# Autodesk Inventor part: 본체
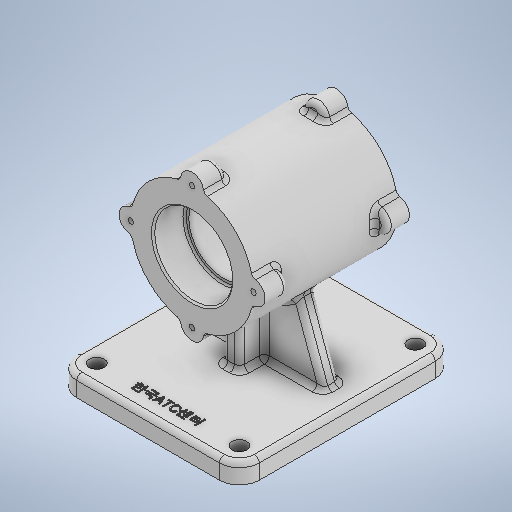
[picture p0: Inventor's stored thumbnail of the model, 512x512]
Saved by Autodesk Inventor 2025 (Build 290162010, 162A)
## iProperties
Created: 2024-08
Part Number: 본체
Material: 일반
Document SubType Name: Modeling
Designer: 학생
Density: 1 g/cm^3
Appearance: 기본값
Author: 학생
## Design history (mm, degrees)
sketch "스케치1"
  geometry: C1 r 37 at (0, 0); 1 further point
  constraints: 1 centre point, 1 coincident
  dimensions: "d0" = 74 diameter of C1
extrude "돌출1" new body sketch "스케치1" stored distance "d1" = 87; taper "d2" = 0 deg
sketch "스케치2"
  geometry: L1 (-90.461, 0)-(90.461, 0); L2 (0, 60.308)-(0, -67.296); C1 r 7 at (0, 37); C2 r 7 at (-37, 0); C3 r 7 at (0, -37); C4 r 7 at (37, 0); 2 further points
  constraints: 4 centre point, 4 end point, 2 point on line, 1 horizontal, 1 midpoint, 1 vertical, 1 vertical alignment, 10 other
  dimensions: "d3" = 14 diameter of C1; "d6" = 360 deg dimension on point (0, 0) C1.centre (derived)
extrude "돌출2" join sketch "스케치2" distance "d8" = 14; taper "d9" = 0 deg
node "작업 평면1"
sketch "스케치3"
  geometry: L1 (55, 70)-(-55, 70); L2 (-55, 70)-(-55, -60); L3 (-55, -60)-(55, -60); L4 (55, -60)-(55, 70); L5 (55, 70)-(-55, -60); L6 (-55, 70)-(55, -60); 2 further points
  constraints: 12 end point, 2 midpoint, 2 parallel, 1 horizontal, 1 perpendicular, 1 vertical alignment
  dimensions: "d11" = 130 distance of L3.end L1.start; "d12" = 110 distance of L2.end L3.end; "d30" = 70 distance from line of L1 point (0, 0)
extrude "돌출3" join sketch "스케치3" distance "d13" = 12; taper "d14" = 0 deg
sketch "스케치5"
  geometry: L1 (-5, 20)-(5, 20); L2 (5, 20)-(5, -20); L3 (5, -20)-(-5, -20); L4 (-5, -20)-(-5, 20); L5 (-55, -70)-(55, -70) reference; 2 further points
  constraints: 8 end point, 2 parallel, 1 horizontal, 1 midpoint, 1 perpendicular, 1 vertical alignment
  dimensions: "d22" = 10 distance of L1.start L1.end; "d23" = 40 distance of L1.end L2.end; "d24" = 50 distance between parallel lines of L5 L3
extrude "돌출5" join sketch "스케치5" stored distance "d25" = 10; taper "d26" = 0 deg
sketch "스케치7"
  geometry: L1 (-22.946, -20.396)-(-41, -70); L2 (55, -70)-(-55, -70) reference; L3 (41, -70)-(22.946, -20.396); L4 (22.946, -20.396)-(-22.946, -20.396); L5 (0, 11.975)-(0, -94.484); L6 (-55, -82)-(-55, -70) reference; 2 further points
  constraints: 8 end point, 3 point on line, 1 midpoint, 1 parallel, 1 vertical, 1 other
  dimensions: "d31" = 110 deg angle of L2 L1; "d32" = 14 horizontal distance of point (-55, -76) L1.end; "d33" = 49.60432 distance between parallel lines of L2 L4
extrude "돌출6" join sketch "스케치7" stored distance "d34" = 10; taper "d35" = 0 deg
sketch "스케치8"
  geometry: A1 r 37 centre (0, 0) between (36.338, 6.969) and (6.969, 36.338) reference; 2 further points
  constraints: 1 coincident
hole "구멍1" sketch "스케치8" at (0, 0) diameter "d36" = 47; stored, may be unused: countersink angle "d40" = 90 deg, drill point angle "d42" = 0 deg; dims "d37" = 6, "d38" = 4, "d39" = 2, "d41" = 19
sketch "스케치9"
  geometry: A1 r 37 centre (0, 0) between (36.338, 6.969) and (6.969, 36.338) reference; 2 further points
  constraints: 1 coincident
hole "구멍2" sketch "스케치9" at (0, 0) diameter "d43" = 47; stored, may be unused: countersink angle "d47" = 90 deg, drill point angle "d49" = 0 deg; dims "d44" = 6, "d45" = 4, "d46" = 2, "d48" = 19
sketch "스케치10"
  geometry: C1 r 23.5 at (0, 0) reference; 2 further points
  constraints: 1 coincident
hole "구멍3" sketch "스케치10" at (0, 0) diameter "d50" = 42; stored, may be unused: countersink angle "d54" = 90 deg, drill point angle "d56" = 0 deg; dims "d51" = 6, "d52" = 4, "d53" = 2, "d55" = 19
fillet "모깎기1" dims "d57" = 12
sketch "스케치11"
  geometry: A1 r 12 centre (43, -58) between (43, -70) and (55, -58) reference; A2 r 12 centre (-43, -58) between (-55, -58) and (-43, -70) reference; A3 r 12 centre (43, 48) between (55, 48) and (43, 60) reference; A4 r 12 centre (-43, 48) between (-43, 60) and (-55, 48) reference; 5 further points
  constraints: 4 coincident
hole "구멍4" sketch "스케치11" at (43, -58), (-43, -58), (43, 48), (-43, 48) diameter "d58" = 9; stored, may be unused: countersink angle "d62" = 90 deg, drill point angle "d64" = 0 deg; dims "d59" = 6, "d60" = 4, "d61" = 2, "d63" = 8
sketch "스케치12" dims "d65" = 74
  geometry: L1 (0, 71.26)-(0, -102.389); L2 (-89.397, 0)-(110.75, 0); 3 further points
  constraints: 4 end point, 3 point on line, 1 coincident, 1 horizontal, 1 vertical, 1 vertical alignment, 2 other
hole "구멍5" sketch "스케치12" at (0, 37) diameter "d66" = 3.242; stored, may be unused: countersink angle "d70" = 90 deg, drill point angle "d72" = 118 deg; dims "d67" = 8, "d68" = 4, "d69" = 2, "d71" = 10
fillet "모깎기2" dims "d76" = 3
fillet "모깎기3" dims "d77" = 3
fillet "모깎기4" dims "d78" = 3
fillet "모깎기5" dims "d79" = 3
fillet "모깎기6" dims "d80" = 3
fillet "모깎기7" dims "d81" = 1
chamfer "모따기1" distance "d82" = 1; stored, may be unused: second distance "d83" = 2, angle "d84" = 45 deg
sketch "스케치13"
  geometry: 2 further points
  constraints: 1 vertical alignment, 1 other
  dimensions: "d85" = 58 distance of point (0, 0) point (0, -58)
feature "엠보싱1" sketch "스케치13" dims "d86" = 0.5, "d87" = 0
feature "ˤ耀˦耀˨耀˪耀ˬ耀ˮ耀˰耀˲耀" dims "d0" = 74, "d1" = 87, "d2" = 0, "d3" = 14, "d4" = 40, "d6" = 360 deg (derived), "d8" = 14, "d9" = 0, "d10" = -82, "d11" = 130, "d12" = 110, "d13" = 12, "d14" = 0, "d22" = 10, "d23" = 40, "d24" = 50, "d25" = 10, "d26" = 0, "d30" = 70, "d31" = 110 deg, "d32" = 14, "d33" = 49.60432, "d34" = 10, "d35" = 0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
node "솔리드1"
mirror "미러1"
pattern_circular "원형 패턴1" dims angle "d74" = 360 deg
mirror "미러2"
node "스케치 - 원형 패턴1" dims "d6" = 360 deg (derived)
feature "A9D066F2-1C7D-4E18-AEED-F7BC21143FA4" dims "d36" = 47, "d37" = 6, "d38" = 4, "d39" = 2, "d40" = 90 deg, "d41" = 19, "d42" = 0
